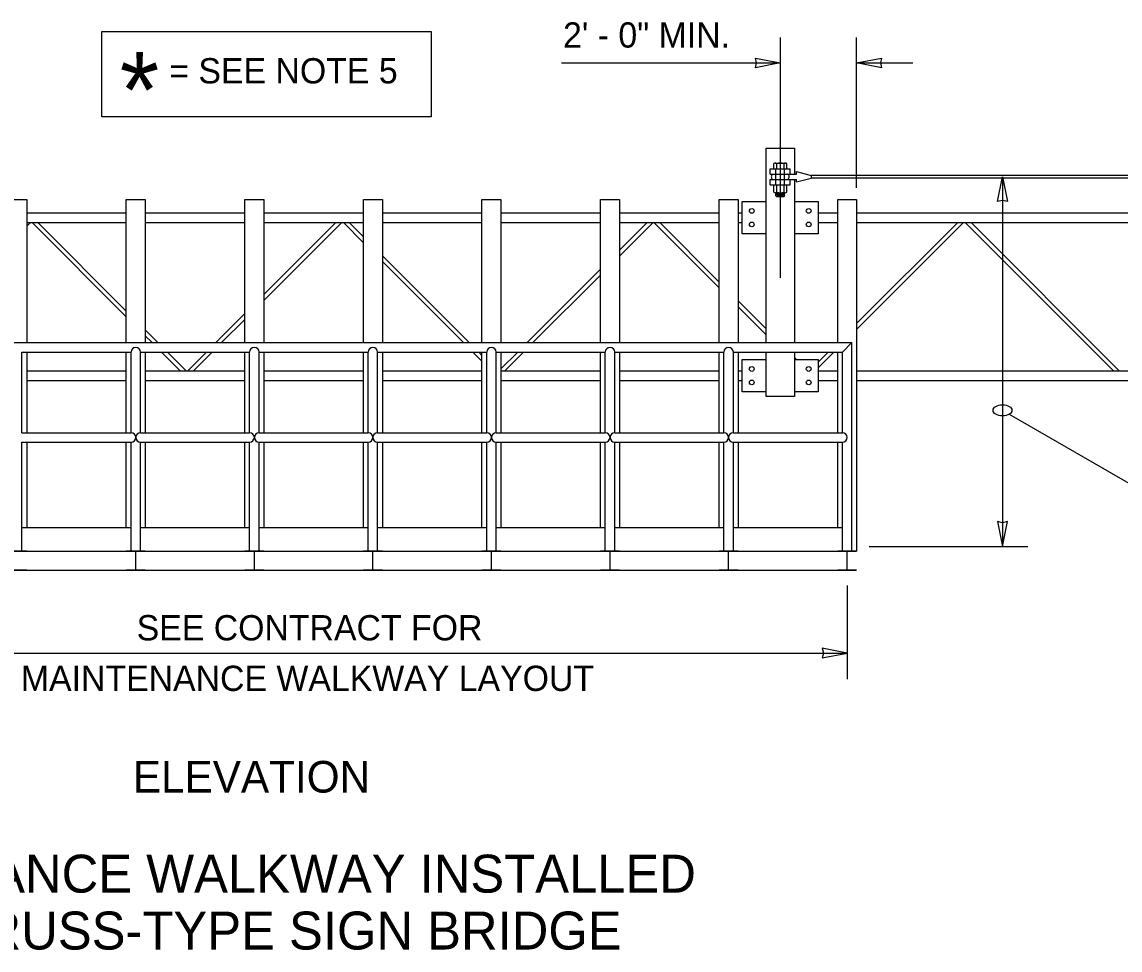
# Model space of a CAD drawing. Extents: x 99862 to 103151, y 100000 to 105076.
# Drawn here: x 101035 to 101730, y 101030 to 101617 of the extents above; entities that cross this region are included whole.
import ezdxf

# ---------------------------------------------------------------- set-up
doc = ezdxf.new("R2010")
doc.units = 0
for name, color, linetype in [('Level 15', 7, 'Continuous'), ('Level 18', 7, 'Continuous'), ('Level 2', 7, 'Continuous'), ('Level 20', 7, 'Continuous'), ('Level 22', 7, 'Continuous'), ('Level 23', 7, 'Continuous'), ('Level 27', 7, 'Continuous'), ('Level 4', 7, 'Continuous'), ('Level 7', 7, 'Continuous')]:
    doc.layers.add(name, color=color, linetype=linetype)

msp = doc.modelspace()

# ---------------------------------------------------------------- linework, layer by layer
at = {"layer": 'Level 15'}
for p, q in [((101514.72, 101607.01), (101514.72, 101455.11)), ((101563.05, 101511.91), (101563.05, 101607.01)), ((101376.39, 101591.01), (101514.72, 101591.01)), ((101563.05, 101591.01), (101598.55, 101591.01)), ((101655.31, 101519.01), (101655.31, 101285.01)), ((101659.55, 101368.72), (101736.69, 101324.18)), ((101571.05, 101285.01), (101671.31, 101285.01)), ((101557.05, 101260.38), (101557.05, 101201.02)), ((100882.05, 101217.57), (101557.05, 101217.57))]:
    msp.add_line(p, q, dxfattribs=at)
for points in [[(101514.72, 101591.01), (101499, 101587.93), (101499.72, 101591.01), (101499, 101594.09)], [(101563.05, 101591.01), (101578.77, 101594.09), (101578.05, 101591.01), (101578.77, 101587.93)], [(101655.31, 101519.01), (101658.39, 101503.28), (101655.31, 101504.01), (101652.22, 101503.28)], [(101655.31, 101285.01), (101658.39, 101300.73), (101655.31, 101300.01), (101652.22, 101300.73)], [(101557.05, 101217.57), (101541.32, 101220.65), (101542.05, 101217.57), (101541.32, 101214.48)]]:
    msp.add_lwpolyline(points, close=True, dxfattribs=at)
msp.add_ellipse((101655.31, 101371.17), major_axis=(-6, 0), ratio=0.57735, dxfattribs=at)
at = {"layer": 'Level 18'}
for points in [[(101505.72, 101537.01), (101505.72, 101537.01), (101523.72, 101537.01), (101523.72, 101520.65)], [(101505.72, 101414.01), (101505.72, 101537.01)], [(101523.72, 101517.33), (101523.72, 101414.01)], [(101505.72, 101482.84), (101490.72, 101482.84), (101490.72, 101503.34), (101505.72, 101503.34)], [(101523.72, 101503.34), (101538.72, 101503.34), (101538.72, 101482.84), (101523.72, 101482.84)], [(101523.72, 101408.01), (101523.72, 101379.97), (101505.72, 101379.97), (101505.72, 101408.01)], [(101505.72, 101382.84), (101490.72, 101382.84), (101490.72, 101403.34), (101505.72, 101403.34)], [(101523.72, 101403.34), (101538.72, 101403.34), (101538.72, 101382.84), (101523.72, 101382.84)]]:
    msp.add_lwpolyline(points, dxfattribs=at)
for centre in [(101496.72, 101497.34), (101532.72, 101497.34), (101496.72, 101488.84), (101532.72, 101488.84), (101496.72, 101397.34), (101532.72, 101397.34), (101496.72, 101388.84), (101532.72, 101388.84)]:
    msp.add_circle(centre, 1.5, dxfattribs=at)
at = {"layer": 'Level 2'}
msp.add_line((101554.05, 101408.01), (101560.05, 101414.01), dxfattribs=at)
for centre, start, end in [((101107.05, 101408.01), 0, 180), ((101182.05, 101408.01), 0, 180), ((101257.05, 101408.01), 0, 180), ((101332.05, 101408.01), 0, 180), ((101407.05, 101408.01), 0, 180), ((101482.05, 101408.01), 0, 180), ((101104.05, 101354.01), 270, 90), ((101110.05, 101354.01), 90, 270), ((101179.05, 101354.01), 270, 90), ((101185.05, 101354.01), 90, 270), ((101254.05, 101354.01), 270, 90), ((101260.05, 101354.01), 90, 270), ((101329.05, 101354.01), 270, 90), ((101335.05, 101354.01), 90, 270), ((101404.05, 101354.01), 270, 90), ((101410.05, 101354.01), 90, 270), ((101479.05, 101354.01), 270, 90), ((101485.05, 101354.01), 90, 270), ((101554.05, 101354.01), 270, 90)]:
    msp.add_arc(centre, 3, start, end, dxfattribs=at)
at = {"layer": 'Level 20'}
msp.add_lwpolyline([(101085.52, 101610.85), (101293.84, 101610.85), (101293.84, 101556.82), (101085.52, 101556.82)], close=True, dxfattribs=at)
at = {"layer": 'Level 22'}
msp.add_line((101563.05, 101443.09), (101563.05, 101282.01), dxfattribs=at)
for points in [[(101026.05, 101414.01), (101026.05, 101504.55), (101038.05, 101504.55), (101038.05, 101414.01)], [(101101.05, 101414.01), (101101.05, 101504.55), (101113.05, 101504.55), (101113.05, 101414.01)], [(101176.05, 101414.01), (101176.05, 101504.55), (101188.05, 101504.55), (101188.05, 101414.01)], [(101251.05, 101414.01), (101251.05, 101504.55), (101263.05, 101504.55), (101263.05, 101414.01)], [(101326.05, 101414.01), (101326.05, 101504.55), (101338.05, 101504.55), (101338.05, 101414.01)], [(101401.05, 101414.01), (101401.05, 101504.55), (101413.05, 101504.55), (101413.05, 101414.01)], [(101476.05, 101414.01), (101476.05, 101504.55), (101488.05, 101504.55), (101488.05, 101414.01)], [(101551.05, 101414.01), (101551.05, 101504.55), (101563.05, 101504.55), (101563.05, 101443.09)], [(101038.05, 101408.01), (101038.05, 101357.01)], [(101101.05, 101357.01), (101101.05, 101408.01)], [(101113.05, 101408.01), (101113.05, 101357.01)], [(101176.05, 101357.01), (101176.05, 101408.01)], [(101188.05, 101408.01), (101188.05, 101357.01)], [(101251.05, 101357.01), (101251.05, 101408.01)], [(101263.05, 101408.01), (101263.05, 101357.01)], [(101326.05, 101357.01), (101326.05, 101408.01)], [(101338.05, 101408.01), (101338.05, 101357.01)], [(101401.05, 101357.01), (101401.05, 101408.01)], [(101413.05, 101408.01), (101413.05, 101357.01)], [(101476.05, 101357.01), (101476.05, 101408.01)], [(101488.05, 101408.01), (101488.05, 101357.01)], [(101551.05, 101357.01), (101551.05, 101408.01)], [(101038.05, 101351.01), (101038.05, 101297.01)], [(101101.05, 101297.01), (101101.05, 101351.01)], [(101113.05, 101351.01), (101113.05, 101297.01)], [(101176.05, 101297.01), (101176.05, 101351.01)], [(101188.05, 101351.01), (101188.05, 101297.01)], [(101251.05, 101297.01), (101251.05, 101351.01)], [(101263.05, 101351.01), (101263.05, 101297.01)], [(101326.05, 101297.01), (101326.05, 101351.01)], [(101338.05, 101351.01), (101338.05, 101297.01)], [(101401.05, 101297.01), (101401.05, 101351.01)], [(101413.05, 101351.01), (101413.05, 101297.01)], [(101476.05, 101297.01), (101476.05, 101351.01)], [(101488.05, 101351.01), (101488.05, 101297.01)], [(101551.05, 101297.01), (101551.05, 101351.01)]]:
    msp.add_lwpolyline(points, dxfattribs=at)
at = {"layer": 'Level 23'}
for p, q in [((101038.05, 101282.01), (101026.05, 101282.01)), ((101113.05, 101282.01), (101101.05, 101282.01)), ((101107.05, 101270.01), (101107.05, 101282.01)), ((101188.05, 101282.01), (101176.05, 101282.01)), ((101182.05, 101270.01), (101182.05, 101282.01)), ((101263.05, 101282.01), (101251.05, 101282.01)), ((101257.05, 101270.01), (101257.05, 101282.01)), ((101338.05, 101282.01), (101326.05, 101282.01)), ((101332.05, 101270.01), (101332.05, 101282.01)), ((101413.05, 101282.01), (101401.05, 101282.01)), ((101407.05, 101270.01), (101407.05, 101282.01)), ((101488.05, 101282.01), (101476.05, 101282.01)), ((101482.05, 101270.01), (101482.05, 101282.01)), ((101563.05, 101282.01), (101551.05, 101282.01)), ((101557.05, 101270.01), (101557.05, 101282.01)), ((101038.05, 101270.01), (101026.05, 101270.01)), ((101113.05, 101270.01), (101101.05, 101270.01)), ((101188.05, 101270.01), (101176.05, 101270.01)), ((101263.05, 101270.01), (101251.05, 101270.01)), ((101338.05, 101270.01), (101326.05, 101270.01)), ((101413.05, 101270.01), (101401.05, 101270.01)), ((101488.05, 101270.01), (101476.05, 101270.01)), ((101563.05, 101270.01), (101551.05, 101270.01))]:
    msp.add_line(p, q, dxfattribs=at)
at = {"layer": 'Level 27'}
for p, q in [((100879.05, 101414.01), (101250.42, 101414.01)), ((101035.05, 101408.01), (101104.05, 101408.01)), ((101035.05, 101357.01), (101035.05, 101408.01)), ((101104.05, 101357.01), (101104.05, 101408.01)), ((101110.05, 101408.01), (101179.05, 101408.01)), ((101110.05, 101357.01), (101110.05, 101408.01)), ((101179.05, 101357.01), (101179.05, 101408.01)), ((101185.05, 101408.01), (101254.05, 101408.01)), ((101185.05, 101357.01), (101185.05, 101408.01)), ((101250.85, 101414.01), (101560.05, 101414.01)), ((101254.05, 101357.01), (101254.05, 101408.01)), ((101260.05, 101408.01), (101329.05, 101408.01)), ((101260.05, 101357.01), (101260.05, 101408.01)), ((101329.05, 101357.01), (101329.05, 101408.01)), ((101335.05, 101408.01), (101404.05, 101408.01)), ((101335.05, 101357.01), (101335.05, 101408.01)), ((101404.05, 101357.01), (101404.05, 101408.01)), ((101410.05, 101408.01), (101479.05, 101408.01)), ((101410.05, 101357.01), (101410.05, 101408.01)), ((101479.05, 101357.01), (101479.05, 101408.01)), ((101485.05, 101408.01), (101554.05, 101408.01)), ((101485.05, 101357.01), (101485.05, 101408.01)), ((101554.05, 101357.01), (101554.05, 101408.01)), ((101560.05, 101282.01), (101560.05, 101414.01)), ((101035.05, 101357.01), (101104.05, 101357.01)), ((101110.05, 101357.01), (101179.05, 101357.01)), ((101185.05, 101357.01), (101254.05, 101357.01)), ((101260.05, 101357.01), (101329.05, 101357.01)), ((101335.05, 101357.01), (101404.05, 101357.01)), ((101410.05, 101357.01), (101479.05, 101357.01)), ((101485.05, 101357.01), (101554.05, 101357.01)), ((101035.05, 101351.01), (101104.05, 101351.01)), ((101035.05, 101282.01), (101035.05, 101351.01)), ((101104.05, 101282.01), (101104.05, 101351.01)), ((101110.05, 101351.01), (101179.05, 101351.01)), ((101110.05, 101282.01), (101110.05, 101351.01)), ((101179.05, 101282.01), (101179.05, 101351.01)), ((101185.05, 101351.01), (101254.05, 101351.01)), ((101185.05, 101282.01), (101185.05, 101351.01)), ((101254.05, 101282.01), (101254.05, 101351.01)), ((101260.05, 101351.01), (101329.05, 101351.01)), ((101260.05, 101282.01), (101260.05, 101351.01)), ((101329.05, 101282.01), (101329.05, 101351.01)), ((101335.05, 101351.01), (101404.05, 101351.01)), ((101335.05, 101282.01), (101335.05, 101351.01)), ((101404.05, 101282.01), (101404.05, 101351.01)), ((101410.05, 101351.01), (101479.05, 101351.01)), ((101410.05, 101282.01), (101410.05, 101351.01)), ((101479.05, 101282.01), (101479.05, 101351.01)), ((101485.05, 101351.01), (101554.05, 101351.01)), ((101485.05, 101282.01), (101485.05, 101351.01)), ((101554.05, 101282.01), (101554.05, 101351.01)), ((101035.05, 101297.01), (101104.05, 101297.01)), ((101110.05, 101297.01), (101179.05, 101297.01)), ((101185.05, 101297.01), (101254.05, 101297.01)), ((101260.05, 101297.01), (101329.05, 101297.01)), ((101335.05, 101297.01), (101404.05, 101297.01)), ((101410.05, 101297.01), (101479.05, 101297.01)), ((101485.05, 101297.01), (101554.05, 101297.01)), ((100876.05, 101282.01), (101563.05, 101282.01)), ((100876.05, 101270.01), (101563.05, 101270.01))]:
    msp.add_line(p, q, dxfattribs=at)
at = {"layer": 'Level 4'}
for p, q in [((101510.61, 101524.02), (101510.61, 101527.4)), ((101511.47, 101527.67), (101517.96, 101527.67)), ((101512.35, 101527.4), (101512.35, 101524.02)), ((101517.09, 101527.4), (101517.09, 101524.02)), ((101518.83, 101524.02), (101518.83, 101527.4)), ((101508.45, 101524.02), (101520.99, 101524.02)), ((101508.45, 101520.65), (101508.45, 101524.02)), ((101508.45, 101520.65), (101525.01, 101520.65)), ((101511.98, 101513.95), (101511.98, 101524.02)), ((101517.46, 101513.95), (101517.46, 101524.02)), ((101520.99, 101520.65), (101520.99, 101524.02)), ((101525.01, 101520.65), (101525.01, 101522.33)), ((101525.01, 101522.33), (101534.34, 101519.84)), ((101534.34, 101519.84), (101534.34, 101518.18)), ((102173.7, 101519.82), (101534.34, 101519.82)), ((101508.45, 101517.33), (101525.01, 101517.33)), ((101508.45, 101513.95), (101508.45, 101517.33)), ((101508.45, 101513.95), (101520.99, 101513.95)), ((101510.61, 101513.95), (101518.83, 101513.95)), ((101510.61, 101509.16), (101510.61, 101513.95)), ((101512.35, 101513.95), (101512.35, 101509.16)), ((101517.09, 101513.95), (101517.09, 101509.16)), ((101518.83, 101509.16), (101518.83, 101513.95)), ((101520.99, 101513.95), (101520.99, 101517.33)), ((101525.01, 101515.69), (101534.34, 101518.18)), ((101525.01, 101515.69), (101525.01, 101517.33)), ((102173.7, 101518.16), (101534.34, 101518.16)), ((101511.47, 101508.88), (101517.96, 101508.88)), ((101511.98, 101506.92), (101511.98, 101508.88)), ((101511.98, 101507.91), (101517.46, 101507.91)), ((101511.98, 101506.92), (101517.46, 101506.92)), ((101511.98, 101506.92), (101512.27, 101506.42)), ((101512.27, 101506.42), (101517.17, 101506.42)), ((101512.81, 101508.41), (101516.63, 101508.41)), ((101512.81, 101507.42), (101516.63, 101507.42)), ((101517.46, 101506.92), (101517.17, 101506.42)), ((101517.46, 101506.92), (101517.46, 101508.88))]:
    msp.add_line(p, q, dxfattribs=at)
for centre, radius, start, end in [((101511.48, 101526.17), 1.5, 54.71987, 125.28013), ((101514.72, 101517.32), 10.35, 76.75036, 103.24964), ((101517.96, 101526.17), 1.5, 54.71987, 125.28013), ((101511.3, 101518.99), 2.22, 131.73582, 228.26418), ((101518.12, 101519.01), 2.22, 311.73582, 48.26418), ((101511.48, 101510.39), 1.5, 234.71987, 305.28013), ((101514.72, 101519.23), 10.35, 256.75036, 283.24964), ((101517.96, 101510.39), 1.5, 234.71987, 305.28013)]:
    msp.add_arc(centre, radius, start, end, dxfattribs=at)
at = {"layer": 'Level 7'}
for p, q in [((101038.05, 101496.21), (101101.05, 101496.21)), ((101113.05, 101496.21), (101176.05, 101496.21)), ((101188.05, 101496.21), (101251.05, 101496.21)), ((101263.05, 101496.21), (101326.05, 101496.21)), ((101338.05, 101496.21), (101401.05, 101496.21)), ((101413.05, 101496.21), (101476.05, 101496.21)), ((101488.05, 101496.21), (101490.72, 101496.21)), ((101538.72, 101496.21), (101551.05, 101496.21)), ((101563.05, 101496.21), (101771.55, 101496.21)), ((101040.37, 101489.96), (101038.05, 101487.64)), ((101038.05, 101489.96), (101101.05, 101489.96)), ((101041.41, 101489.96), (101101.05, 101430.33)), ((101045.09, 101489.96), (101101.05, 101434.01)), ((101113.05, 101489.96), (101176.05, 101489.96)), ((101237.32, 101489.96), (101188.05, 101440.7)), ((101233.64, 101489.96), (101188.05, 101444.38)), ((101188.05, 101489.96), (101251.05, 101489.96)), ((101238.36, 101489.96), (101251.05, 101477.27)), ((101242.04, 101489.96), (101251.05, 101480.96)), ((101263.05, 101489.96), (101326.05, 101489.96)), ((101338.05, 101489.96), (101401.05, 101489.96)), ((101434.27, 101489.96), (101413.05, 101468.75)), ((101430.58, 101489.96), (101413.05, 101472.43)), ((101413.05, 101489.96), (101476.05, 101489.96)), ((101434.77, 101489.96), (101476.05, 101448.68)), ((101438.45, 101489.96), (101476.05, 101452.36)), ((101488.05, 101489.96), (101490.72, 101489.96)), ((101538.72, 101489.96), (101551.05, 101489.96)), ((101563.05, 101489.96), (101771.55, 101489.96)), ((101630.67, 101489.96), (101563.05, 101422.34)), ((101626.99, 101489.96), (101563.05, 101426.02)), ((101631.72, 101489.96), (101725.47, 101396.21)), ((101635.4, 101489.96), (101729.15, 101396.21)), ((101263.05, 101468.96), (101318, 101414.01)), ((101263.05, 101465.27), (101314.32, 101414.01)), ((101401.05, 101460.43), (101354.63, 101414.01)), ((101401.05, 101456.75), (101358.31, 101414.01)), ((101488.05, 101440.36), (101505.72, 101422.69)), ((101488.05, 101436.68), (101505.72, 101419.01)), ((101176.05, 101432.38), (101157.68, 101414.01)), ((101176.05, 101428.7), (101161.36, 101414.01)), ((101113.05, 101422.01), (101121.05, 101414.01)), ((101113.05, 101418.33), (101117.37, 101414.01)), ((101123.37, 101408.01), (101135.16, 101396.21)), ((101127.05, 101408.01), (101138.84, 101396.21)), ((101151.68, 101408.01), (101139.89, 101396.21)), ((101155.36, 101408.01), (101143.57, 101396.21)), ((101320.32, 101408.01), (101326.05, 101402.27)), ((101324, 101408.01), (101326.05, 101405.96)), ((101348.63, 101408.01), (101338.05, 101397.43)), ((101352.31, 101408.01), (101340.52, 101396.21)), ((101548.72, 101408.01), (101538.72, 101398.01)), ((101545.04, 101408.01), (101538.72, 101401.69)), ((101523.72, 101404.69), (101525.08, 101403.34)), ((101038.05, 101396.21), (101101.05, 101396.21)), ((101113.05, 101396.21), (101176.05, 101396.21)), ((101188.05, 101396.21), (101251.05, 101396.21)), ((101263.05, 101396.21), (101326.05, 101396.21)), ((101338.05, 101396.21), (101401.05, 101396.21)), ((101413.05, 101396.21), (101476.05, 101396.21)), ((101488.05, 101396.21), (101490.72, 101396.21)), ((101538.72, 101396.21), (101551.05, 101396.21)), ((101563.05, 101396.21), (101771.55, 101396.21)), ((101038.05, 101389.96), (101101.05, 101389.96)), ((101113.05, 101389.96), (101176.05, 101389.96)), ((101188.05, 101389.96), (101251.05, 101389.96)), ((101263.05, 101389.96), (101326.05, 101389.96)), ((101338.05, 101389.96), (101401.05, 101389.96)), ((101413.05, 101389.96), (101476.05, 101389.96)), ((101488.05, 101389.96), (101490.72, 101389.96)), ((101538.72, 101389.96), (101551.05, 101389.96)), ((101563.05, 101389.96), (101771.55, 101389.96))]:
    msp.add_line(p, q, dxfattribs=at)

# ---------------------------------------------------------------- texts
at = {"layer": 'Level 20'}
for s, height, p in [('2\' - 0" MIN.', 16, (101377.34, 101600.71)), ('*', 48, (101096.92, 101549.94)), (' = SEE NOTE 5', 16, (101122.29, 101578.05)), ('SEE CONTRACT FOR', 16, (101107.61, 101225.57)), ('MAINTENANCE WALKWAY LAYOUT', 16, (101034.36, 101193.57)), (' ELEVATION', 20, (101097.76, 101129.28)), ('MAINTENANCE WALKWAY INSTALLED', 24, (100871.14, 101065.95)), ('ON TRUSS-TYPE SIGN BRIDGE', 24, (100934.72, 101029.95))]:
    msp.add_text(s, height=height, dxfattribs=at).set_placement(p)

doc.saveas('drawing.dxf')
